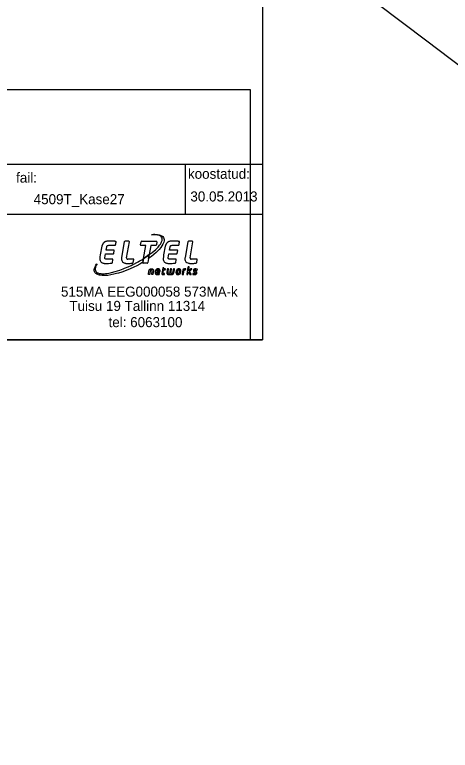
# Model space of a CAD drawing. Extents: x 640876 to 641182, y 6455704 to 6455993.
# Drawn here: x 640991.9 to 641035.3, y 6455745.2 to 6455818.5 of the extents above; entities that cross this region are included whole.
import ezdxf

# ---------------------------------------------------------------- set-up
doc = ezdxf.new("R2010")
doc.units = 0
doc.layers.add('PIIR', color=7, linetype='Continuous')
doc.layers.add('VORMISTUS', color=7, linetype='Continuous')

msp = doc.modelspace()

# ---------------------------------------------------------------- linework, layer by layer
at = {"layer": 'PIIR'}
msp.add_lwpolyline([(640984.64, 6455865.92), (640977.72, 6455857.07), (640984.6, 6455852.08), (640995.15, 6455844.43), (641032.96, 6455815.89), (641051.96, 6455801.51), (641058.78, 6455795.87), (641097.79, 6455765.96), (641114.38, 6455753.24), (641130.25, 6455741.07), (641146.12, 6455728.91), (641143.13, 6455725.04), (641170.91, 6455704.35), (641182.28, 6455716.38), (641177.47, 6455716.39), (641127.83, 6455755.09), (641099.43, 6455777.27), (641081.98, 6455790.7), (641064.46, 6455804.29), (641046.64, 6455817.21), (641029.34, 6455830.8), (641012.04, 6455844.39)], close=True, dxfattribs=at)
at = {"layer": 'VORMISTUS'}
for p, q in [((640924.41, 6455803.627), (641016.602, 6455803.627)), ((641008.897, 6455803.626), (641008.896, 6455798.622)), ((641016.602, 6455803.627), (641016.607, 6455786.126)), ((640924.411, 6455798.631), (641016.602, 6455798.621)), ((641001.302, 6455795.531), (641001.92, 6455795.531)), ((641002.839, 6455795.872), (641002.568, 6455794.332)), ((641003.29, 6455795.93), (641002.908, 6455795.93)), ((641003.06, 6455794.292), (641003.339, 6455795.871)), ((641004.451, 6455795.569), (641004.504, 6455795.872)), ((641004.982, 6455795.522), (641004.49, 6455795.522)), ((641004.573, 6455795.93), (641006.043, 6455795.93)), ((641004.756, 6455794.215), (641004.982, 6455795.522)), ((641005.482, 6455795.522), (641005.323, 6455794.602)), ((641005.968, 6455795.522), (641005.482, 6455795.522)), ((641006.082, 6455795.884), (641006.037, 6455795.581)), ((641007.617, 6455795.531), (641008.235, 6455795.531)), ((641009.161, 6455795.872), (641008.89, 6455794.332)), ((641009.611, 6455795.93), (641009.23, 6455795.93)), ((641009.382, 6455794.292), (641009.661, 6455795.871)), ((641000.895, 6455794.295), (641000.957, 6455794.666)), ((641000.957, 6455794.666), (641001.73, 6455794.666)), ((641001.033, 6455795.061), (641001.084, 6455795.376)), ((641001.788, 6455795.061), (641001.033, 6455795.061)), ((641001.79, 6455794.717), (641001.838, 6455795.003)), ((641007.21, 6455794.295), (641007.272, 6455794.666)), ((641007.272, 6455794.666), (641008.045, 6455794.666)), ((641007.348, 6455795.061), (641007.399, 6455795.376)), ((641008.103, 6455795.061), (641007.348, 6455795.061)), ((641008.105, 6455794.717), (641008.152, 6455795.003)), ((641001.652, 6455794.152), (641000.986, 6455794.152)), ((641001.653, 6455793.813), (641001.703, 6455794.072)), ((641002.568, 6455794.332), (641002.559, 6455794.256)), ((641003.739, 6455794.152), (641003.178, 6455794.152)), ((641003.73, 6455793.816), (641003.778, 6455794.105)), ((641004.683, 6455793.796), (641004.756, 6455794.215)), ((641005.323, 6455794.602), (641005.185, 6455793.807)), ((641007.967, 6455794.152), (641007.301, 6455794.152)), ((641007.967, 6455793.813), (641008.018, 6455794.072)), ((641008.89, 6455794.332), (641008.88, 6455794.256)), ((641010.061, 6455794.152), (641009.5, 6455794.152)), ((641010.052, 6455793.816), (641010.1, 6455794.105)), ((641003.707, 6455793.774), (641003.73, 6455793.816)), ((641005.116, 6455793.749), (641004.723, 6455793.749)), ((641010.029, 6455793.774), (641010.052, 6455793.816)), ((640924.416, 6455786.126), (641016.602, 6455786.126))]:
    msp.add_line(p, q, dxfattribs=at)
for points in [[(640924.107, 6455786.126), (640924.107, 6455929.626), (641016.607, 6455929.626), (641016.607, 6455786.126)], [(641015.363, 6455786.126), (640924.416, 6455786.126), (640924.416, 6455811.035), (641015.363, 6455811.035)], [(641005.323, 6455794.602), (641005.624, 6455794.828), (641005.967, 6455795.128), (641006.194, 6455795.356), (641006.353, 6455795.546), (641006.434, 6455795.659), (641006.5, 6455795.768), (641006.555, 6455795.876), (641006.587, 6455795.956), (641006.605, 6455796.025), (641006.616, 6455796.081), (641006.619, 6455796.166), (641006.609, 6455796.239), (641006.555, 6455796.348), (641006.508, 6455796.393), (641006.439, 6455796.448), (641006.346, 6455796.498), (641006.258, 6455796.532), (641006.172, 6455796.557), (641006.097, 6455796.573), (641006.028, 6455796.58), (641005.868, 6455796.594), (641005.732, 6455796.598), (641005.561, 6455796.589), (641005.734, 6455796.605), (641006.035, 6455796.606), (641006.132, 6455796.6), (641006.32, 6455796.568), (641006.4, 6455796.545), (641006.474, 6455796.518), (641006.532, 6455796.491), (641006.577, 6455796.467), (641006.659, 6455796.405), (641006.736, 6455796.314), (641006.777, 6455796.219), (641006.799, 6455796.113), (641006.799, 6455796.015), (641006.794, 6455795.965), (641006.767, 6455795.848), (641006.681, 6455795.648), (641006.591, 6455795.489), (641006.464, 6455795.304), (641006.303, 6455795.122), (641006.225, 6455795.027), (641006.019, 6455794.82), (641005.779, 6455794.61), (641005.536, 6455794.411), (641005.255, 6455794.209)], [(641000.118, 6455793.701), (641000.038, 6455793.556), (641000.006, 6455793.484), (640999.974, 6455793.394), (640999.953, 6455793.322), (640999.942, 6455793.235), (640999.941, 6455793.133), (640999.951, 6455793.055), (640999.974, 6455792.988), (641000.017, 6455792.907), (641000.076, 6455792.844), (641000.094, 6455792.831), (641000.136, 6455792.804), (641000.195, 6455792.777), (641000.263, 6455792.75), (641000.34, 6455792.731), (641000.395, 6455792.722), (641000.422, 6455792.718), (641000.513, 6455792.709), (641000.562, 6455792.705), (641000.816, 6455792.704), (641000.963, 6455792.717), (641001.112, 6455792.735), (641001.279, 6455792.763), (641001.561, 6455792.822), (641001.922, 6455792.917), (641002.145, 6455792.986), (641002.386, 6455793.067), (641002.553, 6455793.126), (641002.721, 6455793.189), (641002.853, 6455793.238), (641003.22, 6455793.396), (641003.511, 6455793.53), (641003.695, 6455793.619), (641003.843, 6455793.694), (641003.904, 6455793.723), (641003.962, 6455793.755), (641004.077, 6455793.814), (641004.225, 6455793.901), (641004.348, 6455793.969), (641004.447, 6455794.024), (641004.566, 6455794.095), (641004.674, 6455794.163), (641004.756, 6455794.215), (641004.69, 6455793.835), (641004.372, 6455793.652), (641004.076, 6455793.493), (641003.771, 6455793.343), (641003.432, 6455793.188), (641003.031, 6455793.021), (641002.603, 6455792.87), (641002.253, 6455792.761), (641002.07, 6455792.706), (641001.803, 6455792.643), (641001.508, 6455792.584), (641001.182, 6455792.539), (641000.918, 6455792.518), (641000.631, 6455792.518), (641000.429, 6455792.544), (641000.359, 6455792.556), (641000.251, 6455792.584), (641000.201, 6455792.607), (641000.101, 6455792.646), (641000.015, 6455792.707), (640999.953, 6455792.766), (640999.902, 6455792.83), (640999.864, 6455792.914), (640999.848, 6455793.012), (640999.848, 6455793.112), (640999.869, 6455793.223), (640999.905, 6455793.334), (640999.961, 6455793.455), (641000.012, 6455793.548), (641000.082, 6455793.652)], [(641006.832, 6455792.717), (641006.711, 6455792.717), (641006.701, 6455792.729), (641006.696, 6455792.743), (641006.755, 6455793.088), (641006.907, 6455793.087), (641006.914, 6455793.091), (641006.918, 6455793.097), (641006.921, 6455793.109), (641006.926, 6455793.136), (641006.926, 6455793.169), (641006.923, 6455793.174), (641006.913, 6455793.179), (641006.777, 6455793.179), (641006.789, 6455793.256), (641006.79, 6455793.287), (641006.787, 6455793.292), (641006.779, 6455793.293), (641006.771, 6455793.293), (641006.751, 6455793.289), (641006.68, 6455793.273), (641006.666, 6455793.266), (641006.659, 6455793.259), (641006.573, 6455792.737), (641006.573, 6455792.698), (641006.577, 6455792.676), (641006.585, 6455792.665), (641006.599, 6455792.648), (641006.611, 6455792.639), (641006.632, 6455792.63), (641006.653, 6455792.621), (641006.677, 6455792.617), (641006.759, 6455792.617), (641006.814, 6455792.621), (641006.823, 6455792.625), (641006.832, 6455792.63), (641006.836, 6455792.635), (641006.84, 6455792.644), (641006.849, 6455792.684), (641006.849, 6455792.703), (641006.846, 6455792.708), (641006.84, 6455792.713)], [(641009.052, 6455792.625), (641009.163, 6455792.625), (641009.168, 6455792.631), (641009.173, 6455792.637), (641009.177, 6455792.641), (641009.179, 6455792.648), (641009.219, 6455792.877), (641009.35, 6455792.634), (641009.355, 6455792.629), (641009.361, 6455792.625), (641009.489, 6455792.625), (641009.494, 6455792.629), (641009.494, 6455792.648), (641009.339, 6455792.918), (641009.573, 6455793.154), (641009.579, 6455793.165), (641009.579, 6455793.17), (641009.575, 6455793.174), (641009.567, 6455793.179), (641009.456, 6455793.179), (641009.411, 6455793.141), (641009.241, 6455792.963), (641009.236, 6455792.963), (641009.302, 6455793.333), (641009.302, 6455793.364), (641009.299, 6455793.369), (641009.285, 6455793.373), (641009.198, 6455793.373), (641009.185, 6455793.367), (641009.175, 6455793.355), (641009.053, 6455792.664), (641009.05, 6455792.643)], [(641005.675, 6455792.626), (641005.564, 6455792.626), (641005.623, 6455792.994), (641005.623, 6455793.034), (641005.619, 6455793.047), (641005.611, 6455793.06), (641005.606, 6455793.065), (641005.601, 6455793.069), (641005.588, 6455793.078), (641005.556, 6455793.083), (641005.506, 6455793.083), (641005.47, 6455793.079), (641005.447, 6455793.06), (641005.434, 6455793.033), (641005.429, 6455793.012), (641005.365, 6455792.648), (641005.361, 6455792.639), (641005.358, 6455792.634), (641005.349, 6455792.626), (641005.239, 6455792.626), (641005.294, 6455792.983), (641005.307, 6455793.038), (641005.321, 6455793.079), (641005.334, 6455793.097), (641005.362, 6455793.133), (641005.403, 6455793.16), (641005.429, 6455793.174), (641005.475, 6455793.183), (641005.529, 6455793.187), (641005.576, 6455793.187), (641005.616, 6455793.183), (641005.648, 6455793.174), (641005.666, 6455793.165), (641005.689, 6455793.151), (641005.707, 6455793.133), (641005.734, 6455793.101), (641005.747, 6455793.06), (641005.746, 6455792.988), (641005.692, 6455792.649), (641005.688, 6455792.639), (641005.684, 6455792.634), (641005.68, 6455792.629)], [(641006.04, 6455792.86), (641006.374, 6455792.86), (641006.379, 6455792.865), (641006.383, 6455792.874), (641006.387, 6455792.884), (641006.391, 6455792.911), (641006.396, 6455792.943), (641006.396, 6455793.011), (641006.391, 6455793.038), (641006.387, 6455793.061), (641006.382, 6455793.075), (641006.378, 6455793.083), (641006.373, 6455793.092), (641006.369, 6455793.101), (641006.36, 6455793.115), (641006.351, 6455793.124), (641006.342, 6455793.133), (641006.328, 6455793.147), (641006.315, 6455793.156), (641006.296, 6455793.165), (641006.274, 6455793.175), (641006.246, 6455793.183), (641006.15, 6455793.183), (641006.1, 6455793.174), (641006.072, 6455793.161), (641006.046, 6455793.147), (641006.032, 6455793.139), (641006.019, 6455793.129), (641005.99, 6455793.098), (641005.969, 6455793.065), (641005.955, 6455793.039), (641005.941, 6455793.007), (641005.932, 6455792.975), (641005.924, 6455792.934), (641005.92, 6455792.906), (641005.915, 6455792.875), (641005.911, 6455792.825), (641005.911, 6455792.802), (641005.915, 6455792.761), (641005.928, 6455792.72), (641005.946, 6455792.684), (641005.96, 6455792.671), (641005.973, 6455792.657), (641005.991, 6455792.648), (641006.009, 6455792.638), (641006.028, 6455792.629), (641006.059, 6455792.621), (641006.082, 6455792.617), (641006.206, 6455792.617), (641006.27, 6455792.625), (641006.296, 6455792.631), (641006.306, 6455792.634), (641006.315, 6455792.639), (641006.32, 6455792.644), (641006.325, 6455792.653), (641006.328, 6455792.666), (641006.332, 6455792.699), (641006.332, 6455792.731), (641006.227, 6455792.727), (641006.09, 6455792.727), (641006.064, 6455792.743), (641006.053, 6455792.755), (641006.041, 6455792.776), (641006.037, 6455792.79), (641006.034, 6455792.811), (641006.034, 6455792.829)], [(641006.267, 6455792.948), (641006.057, 6455792.948), (641006.057, 6455792.963), (641006.071, 6455793.001), (641006.094, 6455793.041), (641006.112, 6455793.055), (641006.131, 6455793.068), (641006.158, 6455793.073), (641006.221, 6455793.073), (641006.231, 6455793.067), (641006.244, 6455793.058), (641006.253, 6455793.049), (641006.258, 6455793.04), (641006.267, 6455793.022), (641006.272, 6455793), (641006.271, 6455792.954)], [(641007.346, 6455792.731), (641007.256, 6455792.731), (641007.217, 6455792.74), (641007.199, 6455792.764), (641007.19, 6455792.81), (641007.193, 6455792.879), (641007.244, 6455793.16), (641007.239, 6455793.169), (641007.235, 6455793.174), (641007.226, 6455793.178), (641007.143, 6455793.178), (641007.13, 6455793.175), (641007.124, 6455793.166), (641007.121, 6455793.16), (641007.107, 6455793.059), (641007.07, 6455792.843), (641007.066, 6455792.795), (641007.069, 6455792.754), (641007.077, 6455792.729), (641007.086, 6455792.71), (641007.097, 6455792.692), (641007.115, 6455792.669), (641007.128, 6455792.656), (641007.146, 6455792.646), (641007.178, 6455792.629), (641007.206, 6455792.624), (641007.228, 6455792.619), (641007.287, 6455792.619), (641007.324, 6455792.622), (641007.368, 6455792.632), (641007.382, 6455792.638), (641007.409, 6455792.638), (641007.423, 6455792.633), (641007.441, 6455792.629), (641007.491, 6455792.619), (641007.559, 6455792.619), (641007.59, 6455792.623), (641007.622, 6455792.627), (641007.653, 6455792.642), (641007.672, 6455792.652), (641007.7, 6455792.669), (641007.713, 6455792.683), (641007.726, 6455792.696), (641007.736, 6455792.714), (641007.749, 6455792.742), (641007.758, 6455792.764), (641007.763, 6455792.778), (641007.772, 6455792.805), (641007.776, 6455792.818), (641007.785, 6455792.846), (641007.794, 6455792.877), (641007.799, 6455792.9), (641007.803, 6455792.927), (641007.812, 6455792.982), (641007.826, 6455793.058), (641007.841, 6455793.138), (641007.842, 6455793.164), (641007.837, 6455793.171), (641007.826, 6455793.178), (641007.742, 6455793.178), (641007.723, 6455793.162), (641007.718, 6455793.135), (641007.713, 6455793.107), (641007.674, 6455792.878), (641007.669, 6455792.862), (641007.659, 6455792.831), (641007.646, 6455792.795), (641007.632, 6455792.768), (641007.618, 6455792.755), (641007.59, 6455792.74), (641007.567, 6455792.732), (641007.476, 6455792.732), (641007.479, 6455792.759), (641007.504, 6455792.919), (641007.541, 6455793.136), (641007.543, 6455793.169), (641007.529, 6455793.178), (641007.439, 6455793.178), (641007.424, 6455793.166), (641007.419, 6455793.16), (641007.415, 6455793.135), (641007.409, 6455793.107)], [(641008.201, 6455792.617), (641008.278, 6455792.63), (641008.315, 6455792.643), (641008.333, 6455792.653), (641008.351, 6455792.667), (641008.388, 6455792.703), (641008.418, 6455792.748), (641008.442, 6455792.807), (641008.459, 6455792.866), (641008.473, 6455792.952), (641008.473, 6455793.011), (641008.468, 6455793.039), (641008.46, 6455793.075), (641008.446, 6455793.102), (641008.429, 6455793.125), (641008.411, 6455793.143), (641008.392, 6455793.157), (641008.365, 6455793.17), (641008.337, 6455793.18), (641008.323, 6455793.183), (641008.257, 6455793.183), (641008.23, 6455793.179), (641008.2, 6455793.173), (641008.164, 6455793.165), (641008.132, 6455793.151), (641008.095, 6455793.129), (641008.077, 6455793.111), (641008.055, 6455793.084), (641008.033, 6455793.051), (641008.016, 6455793), (641007.984, 6455792.853), (641007.983, 6455792.807), (641007.992, 6455792.753), (641007.998, 6455792.729), (641008.01, 6455792.701), (641008.027, 6455792.679), (641008.041, 6455792.663), (641008.054, 6455792.651), (641008.072, 6455792.639), (641008.094, 6455792.63), (641008.117, 6455792.622), (641008.134, 6455792.618)], [(641008.178, 6455792.726), (641008.218, 6455792.726), (641008.244, 6455792.731), (641008.263, 6455792.74), (641008.276, 6455792.75), (641008.289, 6455792.764), (641008.303, 6455792.786), (641008.317, 6455792.818), (641008.326, 6455792.85), (641008.33, 6455792.864), (641008.335, 6455792.891), (641008.339, 6455792.918), (641008.343, 6455792.95), (641008.343, 6455793.013), (641008.339, 6455793.027), (641008.334, 6455793.036), (641008.33, 6455793.045), (641008.321, 6455793.054), (641008.293, 6455793.067), (641008.275, 6455793.072), (641008.234, 6455793.072), (641008.212, 6455793.067), (641008.175, 6455793.044), (641008.157, 6455793.017), (641008.144, 6455792.991), (641008.13, 6455792.954), (641008.126, 6455792.941), (641008.117, 6455792.891), (641008.108, 6455792.828), (641008.107, 6455792.809), (641008.112, 6455792.778), (641008.126, 6455792.755), (641008.139, 6455792.741), (641008.158, 6455792.732)], [(641008.735, 6455792.66), (641008.811, 6455793.071), (641008.857, 6455793.076), (641008.923, 6455793.078), (641008.932, 6455793.082), (641008.937, 6455793.087), (641008.941, 6455793.109), (641008.95, 6455793.158), (641008.951, 6455793.179), (641008.946, 6455793.184), (641008.939, 6455793.186), (641008.932, 6455793.187), (641008.818, 6455793.178), (641008.776, 6455793.168), (641008.734, 6455793.159), (641008.719, 6455793.152), (641008.705, 6455793.146), (641008.694, 6455793.142), (641008.68, 6455793.093), (641008.605, 6455792.657), (641008.605, 6455792.64), (641008.608, 6455792.632), (641008.616, 6455792.626), (641008.718, 6455792.626), (641008.724, 6455792.632), (641008.729, 6455792.642)], [(641009.659, 6455792.639), (641009.72, 6455792.625), (641009.768, 6455792.617), (641009.889, 6455792.617), (641009.912, 6455792.621), (641009.931, 6455792.626), (641009.944, 6455792.63), (641009.953, 6455792.634), (641009.98, 6455792.647), (641010.008, 6455792.661), (641010.021, 6455792.675), (641010.039, 6455792.695), (641010.053, 6455792.717), (641010.058, 6455792.735), (641010.062, 6455792.762), (641010.062, 6455792.809), (641010.053, 6455792.85), (641010.025, 6455792.886), (641009.98, 6455792.926), (641009.875, 6455792.992), (641009.858, 6455793.01), (641009.846, 6455793.031), (641009.85, 6455793.049), (641009.86, 6455793.061), (641009.882, 6455793.075), (641009.923, 6455793.078), (641010.029, 6455793.069), (641010.087, 6455793.069), (641010.098, 6455793.078), (641010.111, 6455793.128), (641010.11, 6455793.156), (641010.098, 6455793.165), (641009.966, 6455793.183), (641009.886, 6455793.183), (641009.85, 6455793.178), (641009.814, 6455793.17), (641009.782, 6455793.156), (641009.755, 6455793.132), (641009.732, 6455793.106), (641009.719, 6455793.071), (641009.714, 6455793.033), (641009.715, 6455793.019), (641009.719, 6455792.986), (641009.732, 6455792.955), (641009.754, 6455792.928), (641009.777, 6455792.906), (641009.86, 6455792.85), (641009.904, 6455792.818), (641009.918, 6455792.805), (641009.931, 6455792.785), (641009.932, 6455792.756), (641009.919, 6455792.738), (641009.895, 6455792.723), (641009.767, 6455792.723), (641009.681, 6455792.727), (641009.671, 6455792.723), (641009.666, 6455792.718), (641009.66, 6455792.692), (641009.656, 6455792.662), (641009.657, 6455792.648), (641009.657, 6455792.643)]]:
    msp.add_lwpolyline(points, close=True, dxfattribs=at)
for points in [[(641000.613, 6455795.486), (641000.595, 6455795.429), (641000.438, 6455794.569), (641000.412, 6455794.395), (641000.392, 6455794.202), (641000.397, 6455794.106), (641000.425, 6455794.009), (641000.458, 6455793.948), (641000.504, 6455793.888), (641000.541, 6455793.857), (641000.576, 6455793.829), (641000.636, 6455793.798), (641000.673, 6455793.78), (641000.727, 6455793.762), (641000.786, 6455793.744), (641000.845, 6455793.735), (641000.899, 6455793.726), (641001.276, 6455793.725), (641001.436, 6455793.739), (641001.558, 6455793.753), (641001.599, 6455793.762), (641001.622, 6455793.77), (641001.631, 6455793.775), (641001.644, 6455793.788), (641001.649, 6455793.797), (641001.653, 6455793.813)], [(641001.92, 6455795.531), (641001.93, 6455795.536), (641001.939, 6455795.544), (641001.948, 6455795.553), (641001.957, 6455795.567), (641001.966, 6455795.58), (641001.97, 6455795.59), (641001.974, 6455795.613), (641001.979, 6455795.64), (641001.983, 6455795.663), (641001.988, 6455795.69), (641001.993, 6455795.713), (641001.997, 6455795.74), (641002.002, 6455795.767), (641002.006, 6455795.79), (641002.011, 6455795.817), (641002.015, 6455795.839), (641002.015, 6455795.893), (641002.007, 6455795.903), (641001.997, 6455795.912), (641001.988, 6455795.916), (641001.965, 6455795.921), (641001.929, 6455795.925), (641001.888, 6455795.93), (641001.847, 6455795.934), (641001.807, 6455795.939), (641001.765, 6455795.943), (641001.689, 6455795.948), (641001.612, 6455795.953), (641001.403, 6455795.957), (641001.261, 6455795.957), (641001.229, 6455795.952), (641001.193, 6455795.948), (641001.157, 6455795.944), (641001.121, 6455795.939), (641001.103, 6455795.934), (641001.08, 6455795.93), (641001.017, 6455795.916), (641000.986, 6455795.907), (641000.976, 6455795.903), (641000.958, 6455795.894), (641000.927, 6455795.88), (641000.89, 6455795.862), (641000.867, 6455795.848), (641000.854, 6455795.839), (641000.841, 6455795.83), (641000.817, 6455795.812), (641000.799, 6455795.798), (641000.79, 6455795.79), (641000.772, 6455795.771), (641000.75, 6455795.744), (641000.731, 6455795.722), (641000.713, 6455795.699), (641000.7, 6455795.676), (641000.682, 6455795.649), (641000.668, 6455795.622), (641000.659, 6455795.603), (641000.65, 6455795.586), (641000.641, 6455795.563), (641000.632, 6455795.54), (641000.623, 6455795.517), (641000.617, 6455795.498), (641000.613, 6455795.486)], [(641001.084, 6455795.376), (641001.09, 6455795.395), (641001.1, 6455795.418), (641001.107, 6455795.437), (641001.126, 6455795.464), (641001.136, 6455795.477), (641001.159, 6455795.5), (641001.176, 6455795.508), (641001.2, 6455795.517), (641001.218, 6455795.523), (641001.302, 6455795.531)], [(641006.927, 6455795.486), (641006.91, 6455795.429), (641006.753, 6455794.569), (641006.727, 6455794.395), (641006.706, 6455794.202), (641006.712, 6455794.106), (641006.739, 6455794.009), (641006.773, 6455793.948), (641006.819, 6455793.888), (641006.856, 6455793.857), (641006.891, 6455793.829), (641006.951, 6455793.798), (641006.988, 6455793.78), (641007.042, 6455793.762), (641007.101, 6455793.744), (641007.16, 6455793.735), (641007.214, 6455793.726), (641007.591, 6455793.725), (641007.75, 6455793.739), (641007.872, 6455793.753), (641007.914, 6455793.762), (641007.936, 6455793.77), (641007.946, 6455793.775), (641007.959, 6455793.788), (641007.964, 6455793.797), (641007.967, 6455793.813)], [(641008.235, 6455795.531), (641008.245, 6455795.536), (641008.254, 6455795.544), (641008.263, 6455795.553), (641008.272, 6455795.567), (641008.28, 6455795.58), (641008.285, 6455795.59), (641008.289, 6455795.613), (641008.294, 6455795.64), (641008.298, 6455795.663), (641008.303, 6455795.69), (641008.307, 6455795.713), (641008.312, 6455795.74), (641008.316, 6455795.767), (641008.321, 6455795.79), (641008.325, 6455795.817), (641008.33, 6455795.839), (641008.33, 6455795.893), (641008.322, 6455795.903), (641008.312, 6455795.912), (641008.303, 6455795.916), (641008.28, 6455795.921), (641008.244, 6455795.925), (641008.203, 6455795.93), (641008.162, 6455795.934), (641008.122, 6455795.939), (641008.08, 6455795.943), (641008.004, 6455795.948), (641007.926, 6455795.953), (641007.718, 6455795.957), (641007.576, 6455795.957), (641007.544, 6455795.952), (641007.508, 6455795.948), (641007.472, 6455795.944), (641007.436, 6455795.939), (641007.418, 6455795.934), (641007.395, 6455795.93), (641007.332, 6455795.916), (641007.301, 6455795.907), (641007.291, 6455795.903), (641007.273, 6455795.894), (641007.242, 6455795.88), (641007.204, 6455795.862), (641007.182, 6455795.848), (641007.169, 6455795.839), (641007.156, 6455795.83), (641007.132, 6455795.812), (641007.114, 6455795.798), (641007.105, 6455795.79), (641007.087, 6455795.771), (641007.064, 6455795.744), (641007.046, 6455795.722), (641007.028, 6455795.699), (641007.014, 6455795.676), (641006.997, 6455795.649), (641006.982, 6455795.622), (641006.974, 6455795.603), (641006.965, 6455795.586), (641006.955, 6455795.563), (641006.946, 6455795.54), (641006.937, 6455795.517), (641006.932, 6455795.498), (641006.927, 6455795.486)], [(641007.399, 6455795.376), (641007.405, 6455795.395), (641007.415, 6455795.418), (641007.422, 6455795.437), (641007.441, 6455795.464), (641007.451, 6455795.477), (641007.473, 6455795.5), (641007.491, 6455795.508), (641007.515, 6455795.517), (641007.533, 6455795.523), (641007.617, 6455795.531)], [(641000.986, 6455794.152), (641000.945, 6455794.173), (641000.922, 6455794.188), (641000.904, 6455794.21), (641000.899, 6455794.238), (641000.895, 6455794.264), (641000.895, 6455794.295)], [(641001.703, 6455794.072), (641001.703, 6455794.116), (641001.698, 6455794.129), (641001.694, 6455794.133), (641001.68, 6455794.143), (641001.667, 6455794.148), (641001.652, 6455794.152)], [(641004.756, 6455794.215), (641005.002, 6455794.371), (641005.323, 6455794.602)], [(641005.323, 6455794.602), (641005.002, 6455794.371), (641004.756, 6455794.215)], [(641007.301, 6455794.152), (641007.26, 6455794.173), (641007.237, 6455794.188), (641007.219, 6455794.21), (641007.214, 6455794.238), (641007.21, 6455794.264), (641007.21, 6455794.295)], [(641008.018, 6455794.072), (641008.018, 6455794.116), (641008.013, 6455794.129), (641008.009, 6455794.133), (641007.995, 6455794.143), (641007.982, 6455794.148), (641007.967, 6455794.152)], [(641002.75, 6455793.816), (641002.837, 6455793.775), (641002.9, 6455793.757), (641002.972, 6455793.739), (641002.998, 6455793.734), (641003.053, 6455793.725), (641003.304, 6455793.725), (641003.436, 6455793.73), (641003.513, 6455793.738), (641003.626, 6455793.753), (641003.676, 6455793.762), (641003.69, 6455793.767), (641003.698, 6455793.77), (641003.707, 6455793.774)], [(641009.072, 6455793.816), (641009.159, 6455793.775), (641009.221, 6455793.757), (641009.294, 6455793.739), (641009.32, 6455793.734), (641009.375, 6455793.725), (641009.626, 6455793.725), (641009.757, 6455793.73), (641009.834, 6455793.738), (641009.948, 6455793.753), (641009.998, 6455793.762), (641010.011, 6455793.767), (641010.02, 6455793.77), (641010.029, 6455793.774)], [(640924.416, 6455786.126), (641016.602, 6455786.126)]]:
    msp.add_lwpolyline(points, dxfattribs=at)
for centre, major_axis, start_param, end_param in [((641002.908, 6455795.86), (-0.0701, 0), 4.712389, 6.109419), ((641003.29, 6455795.88), (0.0501, 0), 6.108513, 7.853982), ((641004.49, 6455795.562), (-0.0401, 0), 6.110796, 7.853982), ((641004.573, 6455795.86), (-0.0701, 0), 4.712389, 6.110796), ((641005.968, 6455795.592), (0.0701, 0), 4.712389, 6.134349), ((641006.043, 6455795.89), (-0.0401, 0), 2.992757, 4.712389), ((641009.23, 6455795.86), (-0.0701, 0), 4.712389, 6.109419), ((641009.611, 6455795.88), (0.0501, 0), 6.108513, 7.853982), ((641001.73, 6455794.726), (0.0601, 0), 4.712389, 6.118037), ((641001.788, 6455795.011), (0.0501, 0), 6.118037, 7.853982), ((641008.045, 6455794.726), (0.0601, 0), 4.712389, 6.118037), ((641008.103, 6455795.011), (0.0501, 0), 6.118037, 7.853982), ((641002.996, 6455794.183), (0.443, 0), 2.977758, 4.124699), ((641003.178, 6455794.272), (-0.12, 0), 6.108513, 7.853982), ((641003.739, 6455794.112), (0.0401, 0), 6.116836, 7.853982), ((641009.317, 6455794.183), (0.443, 0), 2.977758, 4.124699), ((641009.5, 6455794.272), (-0.12, 0), 6.108513, 7.853982), ((641010.061, 6455794.112), (0.0401, 0), 6.116836, 7.853982), ((641004.723, 6455793.789), (-0.0401, 0), 6.112072, 7.853982), ((641005.116, 6455793.819), (0.0701, 0), 4.712389, 6.112072)]:
    msp.add_ellipse(centre, major_axis=major_axis, ratio=0.997983, start_param=start_param, end_param=end_param, dxfattribs=at)

# ---------------------------------------------------------------- texts
for s, height, p in [('fail:', 0.9997, (640992.057, 6455801.777)), ('koostatud:', 0.9997, (641009.177, 6455802.157)), ('4509T_Kase27', 0.99972, (640993.807, 6455799.627)), ('30.05.2013', 0.9997, (641009.417, 6455799.897)), ('515MA EEG000058 573MA-k', 0.99966, (640996.527, 6455790.417)), ('Tuisu 19 Tallinn 11314', 0.99966, (640997.368, 6455788.997)), ('tel: 6063100', 0.99966, (641001.267, 6455787.377))]:
    msp.add_text(s, height=height, rotation=359.99742, dxfattribs=at).set_placement(p)

doc.saveas('drawing.dxf')
